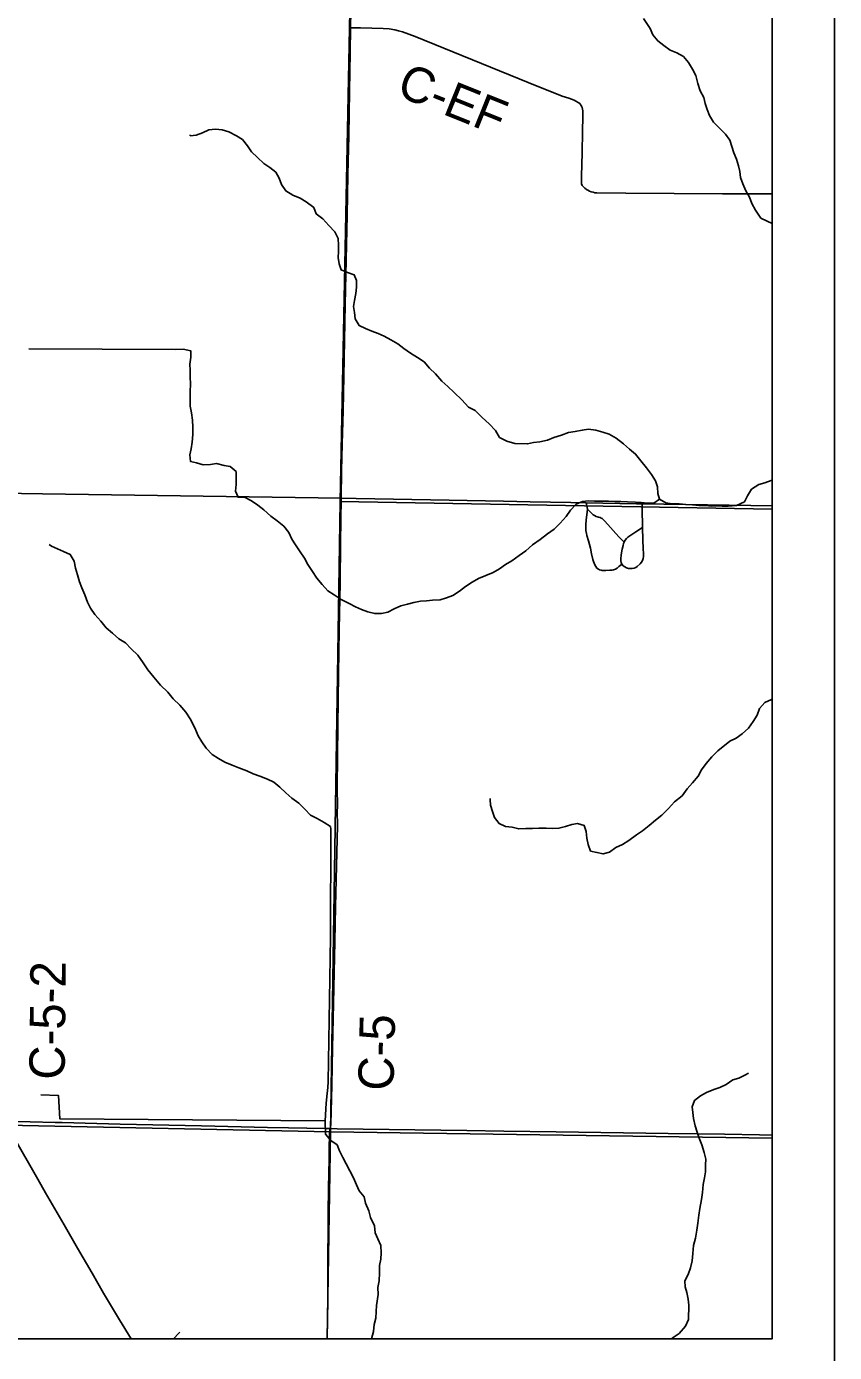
# Model space of a CAD drawing. Extents: x -21.7 to 34, y 0 to 22.
# Drawn here: x 29.12 to 30.417, y 14.078 to 16.205 of the extents above; entities that cross this region are included whole.
import ezdxf

# ---------------------------------------------------------------- set-up
doc = ezdxf.new("R2010")
doc.units = 0
for name, color, linetype in [('Default', 7, 'Continuous'), ('GM_X_County_Road', 7, 'Continuous'), ('GM_X_County_Road_Text', 7, 'Continuous'), ('GM_X_Interchange_Ramps', 7, 'Continuous'), ('GM_X_Minor_River', 7, 'Continuous'), ('GM_X_Township_Road', 7, 'Continuous'), ('SH_Data', 7, 'Continuous')]:
    doc.layers.add(name, color=color, linetype=linetype)

msp = doc.modelspace()

# ---------------------------------------------------------------- linework, layer by layer
at = {"layer": 'Default'}
for points in [[(30.3167, 15.4308), (30.3167, 16.4352), (29.6434, 16.4466), (29.6236, 15.4431)], [(30.3167, 14.4214), (30.3167, 15.4308), (29.6236, 15.4431), (29.6079, 14.4319), (30.0933, 14.425)], [(28.6, 14.1), (29.6028, 14.1), (29.6079, 14.4319), (29.0878, 14.4424), (28.6048, 14.4532)], [(29.6028, 14.1), (30.3167, 14.1), (30.3167, 14.4214), (30.0933, 14.425), (29.6079, 14.4319)]]:
    msp.add_lwpolyline(points, close=True, dxfattribs=at)
at = {"layer": 'GM_X_County_Road'}
for p, q in [((29.6403, 16.2028), (29.6407, 16.23)), ((29.0861, 14.4487), (29.1664, 14.4468))]:
    msp.add_line(p, q, dxfattribs=at)
for points in [[(29.6251, 15.4481), (29.626, 15.4919), (29.6271, 15.5354), (29.6282, 15.5883), (29.63, 15.6721), (29.6319, 15.7591), (29.6349, 15.902), (29.6362, 15.9673), (29.6373, 16.0295), (29.6385, 16.101), (29.6397, 16.1632), (29.6403, 16.2028)], [(29.6403, 16.2028), (29.6421, 16.2028), (29.6533, 16.2024), (29.6563, 16.2024), (29.6927, 16.2016), (29.702, 16.201), (29.7113, 16.1996), (29.7174, 16.1981), (29.7234, 16.1962), (29.7438, 16.1885), (29.7897, 16.1698), (29.925, 16.115), (29.9799, 16.0932), (29.9907, 16.0897), (29.9991, 16.0866), (30.008, 16.0813), (30.011, 16.0769), (30.0118, 16.075), (30.0129, 16.0695), (30.0127, 16.0603), (30.0126, 16.0362), (30.0119, 16.002), (30.0107, 15.9646), (30.0106, 15.9553), (30.0109, 15.9523), (30.0121, 15.9497), (30.0139, 15.9474), (30.016, 15.9454), (30.0186, 15.9434), (30.0209, 15.942), (30.0236, 15.9407), (30.0264, 15.9396), (30.0294, 15.9388), (30.0324, 15.9382), (30.0354, 15.9379), (30.0818, 15.9377), (30.2372, 15.9364), (30.29, 15.9364), (30.3167, 15.9362)], [(29.6076, 14.4369), (29.6082, 14.4405), (29.6085, 14.4429), (29.6086, 14.4452), (29.6092, 14.4638), (29.6101, 14.5074), (29.6115, 14.5664), (29.6124, 14.613), (29.6151, 14.7373), (29.6164, 14.793), (29.6191, 14.9234), (29.6188, 14.945), (29.6191, 14.9543), (29.6189, 14.983), (29.6196, 15.0357), (29.6201, 15.0823), (29.6212, 15.1662), (29.6222, 15.2374), (29.623, 15.2871), (29.6234, 15.312), (29.624, 15.3771), (29.6251, 15.4481)], [(29.1664, 14.4468), (29.1774, 14.4466), (29.2333, 14.4453), (29.2706, 14.4443), (29.4011, 14.4413), (29.5068, 14.4389), (29.541, 14.4382), (29.5997, 14.437), (29.6076, 14.4369)], [(29.6029, 14.1), (29.6037, 14.1615), (29.6037, 14.1926), (29.6041, 14.2299), (29.6044, 14.2766), (29.6044, 14.3014), (29.605, 14.3417), (29.606, 14.388), (29.6059, 14.4065), (29.6063, 14.4251), (29.6067, 14.4296), (29.6072, 14.4344), (29.6076, 14.4369)], [(29.6076, 14.4369), (29.6187, 14.4366), (29.8269, 14.4338), (29.886, 14.433), (29.9699, 14.432), (30.1501, 14.4293), (30.1968, 14.4284), (30.2403, 14.4279), (30.2962, 14.4268), (30.3167, 14.4265)]]:
    msp.add_lwpolyline(points, dxfattribs=at)
at = {"layer": 'GM_X_Interchange_Ramps'}
msp.add_lwpolyline([(27.5987, 14.1), (30.3167, 14.1), (30.3167, 18.4589), (30.0914, 18.462), (29.7432, 18.4669), (29.6813, 18.468), (29.6189, 18.4691), (29.42, 18.4733), (29.1776, 18.4784), (29.1702, 18.4785), (29.019, 18.4799)], dxfattribs=at)
at = {"layer": 'GM_X_Minor_River'}
for points in [[(30.3167, 15.8887), (30.3088, 15.8925), (30.2987, 15.8972), (30.2899, 15.91), (30.284, 15.9211), (30.2804, 15.931), (30.2746, 15.941), (30.2695, 15.9525), (30.2659, 15.9625), (30.2646, 15.972), (30.2629, 15.9815), (30.2597, 15.9922), (30.2553, 16.0022), (30.2521, 16.0125), (30.2486, 16.0224), (30.2416, 16.032), (30.2323, 16.0417), (30.2226, 16.0514), (30.216, 16.0622), (30.2124, 16.0717), (30.2092, 16.0813), (30.2071, 16.0908), (30.2013, 16.1016), (30.1977, 16.1134), (30.1942, 16.1264), (30.1891, 16.1364), (30.1825, 16.1468), (30.1743, 16.1568), (30.1635, 16.1627), (30.1533, 16.1671), (30.1429, 16.1741), (30.1332, 16.1816), (30.125, 16.1912), (30.1211, 16.2015), (30.1103, 16.2177)], [(29.8402, 15.5891), (29.8297, 15.5942), (29.819, 15.6058), (29.8067, 15.6175), (29.7963, 15.6272), (29.7866, 15.6361), (29.7766, 15.6477), (29.767, 15.6566), (29.7585, 15.6667), (29.7476, 15.6737), (29.7364, 15.6808), (29.7259, 15.6882), (29.7159, 15.696), (29.705, 15.7023), (29.6941, 15.7082), (29.6844, 15.7122), (29.6742, 15.7162), (29.6644, 15.7202), (29.6539, 15.725), (29.6477, 15.7361), (29.6464, 15.746), (29.6451, 15.7555), (29.6464, 15.7654), (29.6489, 15.7763), (29.6499, 15.7865), (29.6501, 15.7972), (29.6461, 15.8067), (29.6356, 15.81), (29.6254, 15.8144), (29.6218, 15.8239), (29.6205, 15.8342), (29.6211, 15.8441), (29.6209, 15.854), (29.6204, 15.8646), (29.6149, 15.8753), (29.6056, 15.8858), (29.596, 15.8962), (29.5852, 15.9044), (29.5816, 15.9144), (29.5693, 15.9233), (29.5595, 15.9292), (29.5479, 15.9344), (29.5366, 15.9411), (29.5297, 15.9515), (29.5257, 15.9614), (29.5206, 15.971), (29.5109, 15.9784), (29.5012, 15.9851), (29.4911, 15.9948), (29.4815, 16.0037), (29.4748, 16.0133), (29.4671, 16.0234), (29.4573, 16.0293), (29.445, 16.0356), (29.4341, 16.0392), (29.4235, 16.0402), (29.4132, 16.0389), (29.4029, 16.0342), (29.3926, 16.0306), (29.3831, 16.0296), (29.3828, 16.0311)], [(29.3592, 15.6865), (29.1244, 15.6878)], [(30.1359, 15.4464), (30.1271, 15.4401), (30.1161, 15.4404), (30.1064, 15.4411), (30.0973, 15.4419), (30.0847, 15.4421), (30.0737, 15.4431), (30.0642, 15.4429), (30.054, 15.4435), (30.0436, 15.4432), (30.0317, 15.4436), (30.0218, 15.4442), (30.0123, 15.4428), (30.0024, 15.4388), (29.9931, 15.4292), (29.9861, 15.419), (29.9764, 15.4082), (29.9667, 15.3986), (29.9564, 15.3908), (29.9444, 15.3819), (29.9321, 15.3734), (29.9213, 15.3638), (29.911, 15.356), (29.899, 15.3475), (29.8887, 15.342), (29.8791, 15.3346), (29.8691, 15.3288), (29.8573, 15.3244), (29.8454, 15.3194), (29.8355, 15.3135), (29.8247, 15.3065), (29.8151, 15.2991), (29.8044, 15.2921), (29.7941, 15.2881), (29.7838, 15.2849), (29.772, 15.2844), (29.7622, 15.2838), (29.7523, 15.2829), (29.742, 15.2808), (29.7314, 15.2784), (29.7207, 15.2756), (29.71, 15.2705), (29.7, 15.2653), (29.6898, 15.2633), (29.6792, 15.2631), (29.6678, 15.266), (29.6581, 15.2696), (29.6483, 15.274), (29.6382, 15.2791), (29.6251, 15.2855), (29.6138, 15.2929), (29.6041, 15.2996), (29.5949, 15.3096), (29.586, 15.32), (29.5794, 15.3308), (29.572, 15.342), (29.5662, 15.352), (29.5592, 15.3624), (29.5518, 15.3731), (29.5463, 15.3827), (29.5412, 15.3931), (29.5331, 15.4035), (29.5223, 15.4121), (29.5126, 15.4191), (29.5014, 15.4296), (29.4913, 15.437), (29.4813, 15.444), (29.47, 15.4496), (29.4598, 15.4498), (29.4558, 15.4597), (29.4568, 15.47), (29.457, 15.4806), (29.4568, 15.4909), (29.4471, 15.499), (29.4373, 15.5004), (29.4252, 15.5036), (29.4154, 15.5023), (29.404, 15.5018), (29.3931, 15.5051), (29.3833, 15.5071), (29.3827, 15.5178), (29.3848, 15.5276), (29.3862, 15.5378), (29.3872, 15.5504), (29.3874, 15.5621), (29.3869, 15.5735), (29.3852, 15.5853), (29.3832, 15.596), (29.383, 15.6093), (29.3832, 15.6192), (29.3835, 15.6309), (29.383, 15.6427), (29.3828, 15.6533), (29.3822, 15.6632), (29.3843, 15.6742), (29.3842, 15.6844), (29.3717, 15.687), (29.3592, 15.6865)], [(30.3167, 15.477), (30.3153, 15.4766), (30.305, 15.473), (30.2951, 15.4702), (30.2836, 15.4624), (30.2769, 15.4519), (30.2722, 15.4421), (30.2597, 15.4367), (30.2463, 15.4354), (30.2366, 15.4354), (30.2295, 15.4357), (30.2201, 15.4356), (30.2088, 15.4366), (30.1989, 15.4364), (30.189, 15.4376), (30.1781, 15.438), (30.1675, 15.4391), (30.1562, 15.4392), (30.146, 15.4409), (30.1359, 15.4464), (30.1334, 15.4559), (30.1325, 15.4662), (30.1293, 15.4762), (30.123, 15.4862), (30.1153, 15.4969), (30.1061, 15.5081), (30.0976, 15.5189), (30.0879, 15.5267), (30.0782, 15.5353), (30.0663, 15.5443), (30.0554, 15.5509), (30.0449, 15.5542), (30.0339, 15.5571), (30.0222, 15.5588), (30.012, 15.5571), (30.0009, 15.5554), (29.9899, 15.5534), (29.9785, 15.5494), (29.9663, 15.5455), (29.956, 15.5415), (29.9442, 15.5387), (29.9339, 15.5374), (29.9244, 15.5353), (29.9036, 15.5358), (29.8912, 15.5398), (29.8795, 15.5457), (29.8726, 15.5569), (29.8629, 15.5677), (29.8514, 15.5778), (29.8402, 15.5891)], [(29.6089, 14.9175), (29.6079, 14.9213), (29.5982, 14.9279), (29.5866, 14.9346), (29.5761, 14.9398), (29.5668, 14.9494), (29.5571, 14.9591), (29.5463, 14.9669), (29.5366, 14.9755), (29.527, 14.9844), (29.5173, 14.9926), (29.5071, 14.9974), (29.4947, 15.0025), (29.4842, 15.0062), (29.4737, 15.0106), (29.4613, 15.0157), (29.4504, 15.0201), (29.4387, 15.0246), (29.4286, 15.0305), (29.4185, 15.0371), (29.4089, 15.0472), (29.4015, 15.0576), (29.3957, 15.0672), (29.3906, 15.0798), (29.3829, 15.0944), (29.3763, 15.1048), (29.3663, 15.116), (29.3559, 15.1265), (29.3474, 15.1369), (29.3355, 15.1481), (29.3248, 15.1613), (29.3152, 15.1729), (29.3078, 15.184), (29.299, 15.1963), (29.2886, 15.2064), (29.2793, 15.2161), (29.2685, 15.2228), (29.2584, 15.2317), (29.2484, 15.2403), (29.2395, 15.2511), (29.2298, 15.2615), (29.2232, 15.2719), (29.2181, 15.2815), (29.2138, 15.2934), (29.2091, 15.3045), (29.2055, 15.314), (29.2023, 15.3251), (29.1988, 15.3358), (29.1967, 15.3473), (29.1905, 15.358), (29.18, 15.3628), (29.1702, 15.3672), (29.1604, 15.3711), (29.1567, 15.3739)], [(30.3167, 15.1259), (30.3154, 15.1253), (30.3047, 15.1206), (30.2966, 15.1109), (30.2926, 15.1), (30.2863, 15.0899), (30.2789, 15.0794), (30.2685, 15.0701), (30.2589, 15.0635), (30.2486, 15.0583), (30.2293, 15.0428), (30.2197, 15.0335), (30.2107, 15.0227), (30.2033, 15.0126), (30.1982, 15.0024), (30.1889, 14.9916), (30.1804, 14.9819), (30.1722, 14.9707), (30.1602, 14.961), (30.1506, 14.9506), (30.1397, 14.9398), (30.1293, 14.9316), (30.1193, 14.9231), (30.1089, 14.9146), (30.0993, 14.908), (30.087, 14.8991), (30.0767, 14.8925), (30.066, 14.8877), (30.0556, 14.8804), (30.0453, 14.8775), (30.0355, 14.88), (30.0253, 14.8821), (30.0217, 14.8928), (30.0193, 14.9027), (30.0184, 14.9134), (30.0151, 14.9229), (30.0046, 14.9266), (29.9951, 14.9249), (29.9852, 14.9216), (29.9745, 14.9188), (29.9639, 14.9183), (29.9541, 14.9189), (29.9423, 14.9187), (29.9321, 14.9185), (29.9215, 14.9184), (29.9101, 14.9178), (29.8996, 14.9203), (29.889, 14.9217), (29.8785, 14.9265), (29.8711, 14.9361), (29.8679, 14.9457), (29.8647, 14.9556), (29.8645, 14.9651), (29.8645, 14.9666)], [(29.5995, 14.4495), (29.6012, 14.4779), (29.6027, 14.4931), (29.604, 14.5029), (29.6042, 14.512), (29.6081, 14.7443), (29.6089, 14.9175)], [(30.2099, 14.3787), (30.2101, 14.3882), (30.2076, 14.3988), (30.2041, 14.4107), (30.1998, 14.4218), (30.1966, 14.4313), (30.1933, 14.4413), (30.1906, 14.4531), (30.1892, 14.4626), (30.1883, 14.4721), (30.1923, 14.4823), (30.2019, 14.4897), (30.2115, 14.4948), (30.2229, 14.4995), (30.2328, 14.5031), (30.2428, 14.5079), (30.2536, 14.5153), (30.2631, 14.5177), (30.273, 14.5228), (30.2788, 14.5258)], [(29.5995, 14.4495), (29.1738, 14.4527), (29.1719, 14.49), (29.1435, 14.4909)], [(29.6279, 14.3904), (29.6228, 14.4011), (29.6188, 14.4107), (29.6088, 14.4181), (29.6002, 14.4278), (29.5995, 14.4495)], [(29.6738, 14.1), (29.6772, 14.1115), (29.6782, 14.1228), (29.6807, 14.133), (29.6813, 14.1437), (29.6818, 14.1531), (29.6845, 14.1709), (29.6843, 14.1819), (29.686, 14.1929), (29.6867, 14.2058), (29.6869, 14.2172), (29.689, 14.2274), (29.6892, 14.2377), (29.6887, 14.2494), (29.684, 14.2602), (29.6796, 14.2698), (29.6787, 14.2808), (29.6722, 14.2942), (29.6694, 14.3049), (29.6643, 14.3175), (29.6619, 14.3275), (29.6541, 14.3371), (29.6501, 14.3467), (29.645, 14.3582), (29.6392, 14.3693), (29.633, 14.3804), (29.6279, 14.3904)], [(30.155, 14.1), (30.1562, 14.101), (30.1677, 14.1084), (30.1778, 14.12), (30.1825, 14.1305), (30.183, 14.1537), (30.1817, 14.1636), (30.18, 14.1739), (30.1772, 14.1834), (30.1766, 14.1929), (30.1821, 14.203), (30.1857, 14.2136), (30.1882, 14.225), (30.1896, 14.2367), (30.1906, 14.2492), (30.1939, 14.2613), (30.196, 14.2738), (30.1974, 14.2855), (30.1992, 14.298), (30.2009, 14.3086), (30.2035, 14.3234), (30.2048, 14.3344), (30.2062, 14.3472), (30.208, 14.3578), (30.21, 14.3677), (30.2099, 14.3787)], [(29.3563, 14.1), (29.365, 14.109), (29.3665, 14.1105)]]:
    msp.add_lwpolyline(points, dxfattribs=at)
at = {"layer": 'GM_X_Township_Road'}
msp.add_line((30.0202, 15.4304), (30.0181, 15.4406), dxfattribs=at)
for points in [[(29.0812, 15.4562), (29.1122, 15.4558), (29.1459, 15.4553), (29.6251, 15.4481)], [(29.6251, 15.4481), (29.6494, 15.4477), (29.7986, 15.4451), (29.8857, 15.4432), (29.9282, 15.4424), (29.9935, 15.4411), (30.0181, 15.4406)], [(30.0757, 15.3424), (30.0722, 15.3398), (30.0705, 15.3385), (30.0678, 15.336), (30.0652, 15.3342), (30.0624, 15.3333), (30.0595, 15.3327), (30.0563, 15.3325), (30.0501, 15.3324), (30.0439, 15.3324), (30.0423, 15.3327), (30.0396, 15.3334), (30.038, 15.3341), (30.0356, 15.3361), (30.0338, 15.3385), (30.0322, 15.3411), (30.0309, 15.3439), (30.0298, 15.3468), (30.0288, 15.3498), (30.0267, 15.3589), (30.0251, 15.368), (30.0237, 15.3738), (30.0219, 15.3797), (30.0193, 15.3884), (30.0186, 15.3913), (30.0179, 15.3963), (30.0175, 15.4006), (30.0176, 15.406), (30.0181, 15.4129), (30.0202, 15.4304)], [(30.0181, 15.4406), (30.0991, 15.439), (30.1079, 15.4389), (30.2824, 15.4363), (30.3167, 15.4357)], [(30.0791, 15.3776), (30.075, 15.3818), (30.0707, 15.3862), (30.048, 15.4113), (30.046, 15.4137), (30.0437, 15.4157), (30.0426, 15.4164), (30.041, 15.4172), (30.038, 15.4179), (30.0345, 15.419), (30.0317, 15.4202), (30.0295, 15.4216), (30.0267, 15.424), (30.0202, 15.4304)], [(30.1084, 15.4013), (30.108, 15.4315), (30.1079, 15.4389)], [(30.0757, 15.3424), (30.0779, 15.3398), (30.0805, 15.338), (30.0832, 15.3366), (30.0861, 15.3355), (30.0892, 15.3352), (30.0923, 15.3353), (30.0952, 15.3357), (30.0979, 15.3369), (30.1002, 15.3388), (30.1049, 15.3429), (30.1068, 15.3454), (30.1089, 15.3483), (30.1099, 15.3513), (30.1105, 15.3548), (30.1101, 15.3602), (30.1099, 15.3664), (30.109, 15.3818), (30.1084, 15.4005), (30.1084, 15.4013)], [(30.0791, 15.3776), (30.0793, 15.3782), (30.0809, 15.3809), (30.0829, 15.3833), (30.0851, 15.3854), (30.0901, 15.3891), (30.0979, 15.3943), (30.1084, 15.4013)], [(30.0757, 15.3424), (30.0744, 15.3448), (30.0737, 15.3478), (30.0737, 15.3509), (30.0743, 15.3571), (30.076, 15.3663), (30.0774, 15.3723), (30.0782, 15.3753), (30.0791, 15.3776)], [(29.2884, 14.1), (29.2697, 14.1303), (29.2442, 14.1729), (29.2257, 14.2051), (29.202, 14.2452), (29.1806, 14.2827), (29.1508, 14.3339), (29.1386, 14.3557), (29.0987, 14.4258), (29.0953, 14.4318), (29.0926, 14.4371), (29.0861, 14.4487)], [(29.6029, 14.1), (29.6037, 14.1615), (29.6037, 14.1926), (29.6041, 14.2299), (29.6044, 14.2766), (29.6044, 14.3014), (29.605, 14.3417), (29.606, 14.388), (29.6059, 14.4065), (29.6063, 14.4251), (29.6067, 14.4296), (29.6072, 14.4344), (29.6076, 14.4369)]]:
    msp.add_lwpolyline(points, dxfattribs=at)
at = {"layer": 'SH_Data'}
for p in [(30.3167, 20.9), (23.5167, 14.1)]:
    msp.add_line(p, (30.3167, 14.1), dxfattribs=at)
for points in [[(23.4167, 21), (30.4167, 21), (30.4167, 14), (23.4167, 14)], [(23.5167, 20.9), (30.3167, 20.9), (30.3167, 14.1), (23.5167, 14.1)]]:
    msp.add_lwpolyline(points, close=True, dxfattribs=at)

# ---------------------------------------------------------------- texts
at = {"layer": 'GM_X_County_Road_Text'}
for s, rotation, p in [('C-EF', 338.0803, (29.7117, 16.095)), ('C-5-2', 89.4184, (29.1816, 14.5152)), ('C-5', 88.6522, (29.7091, 14.4973))]:
    msp.add_text(s, height=0.05682, rotation=rotation, dxfattribs=at).set_placement(p)

doc.saveas('drawing.dxf')
